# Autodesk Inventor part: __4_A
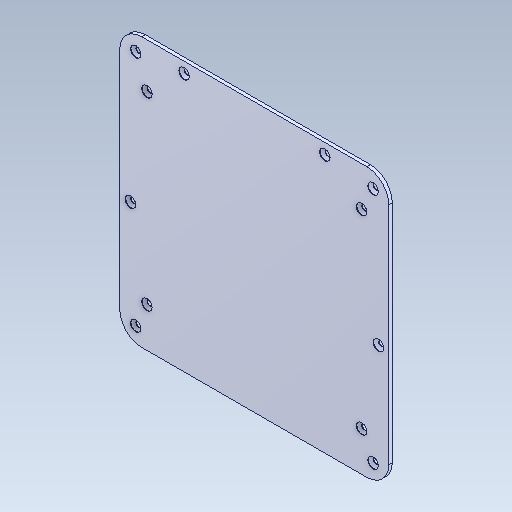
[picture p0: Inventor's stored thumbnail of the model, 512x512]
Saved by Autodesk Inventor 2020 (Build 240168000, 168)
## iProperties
Created: 2017-09
Part Number: __4_A
Material: Générique
Document SubType Name: Modeling
Designer: bruno
Density: 1 g/cm^3
Appearance: Par défaut
Author: bruno
Sending System: SolidWorks 2016
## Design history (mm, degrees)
feature "Importée1"
node "Solide1"
